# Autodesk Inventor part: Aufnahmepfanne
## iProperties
Shininess: 64.0
Length Units: 11269
Angle Units: 11279
Time Units: 11290
Mass Units: 11283
Length Display Precision: 3
Angle Display Precision: 2
Compacted: True
Part Number: Aufnahmepfanne
Document SubType Name: Modeling
Created: 2005-08
Material: Standard
Designer: Kumpf
Density: 0.0
Volumn: 0.0
Area: 0.0
PropertySet Name: Model Information
Control State: 0
Master: False
Checked Out: False
Author: Kumpf
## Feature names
1. Extrusion1
2. Bohrung1 [Hole]
3. Bohrung2 [Hole]
4. Fase1 [Chamfer]
